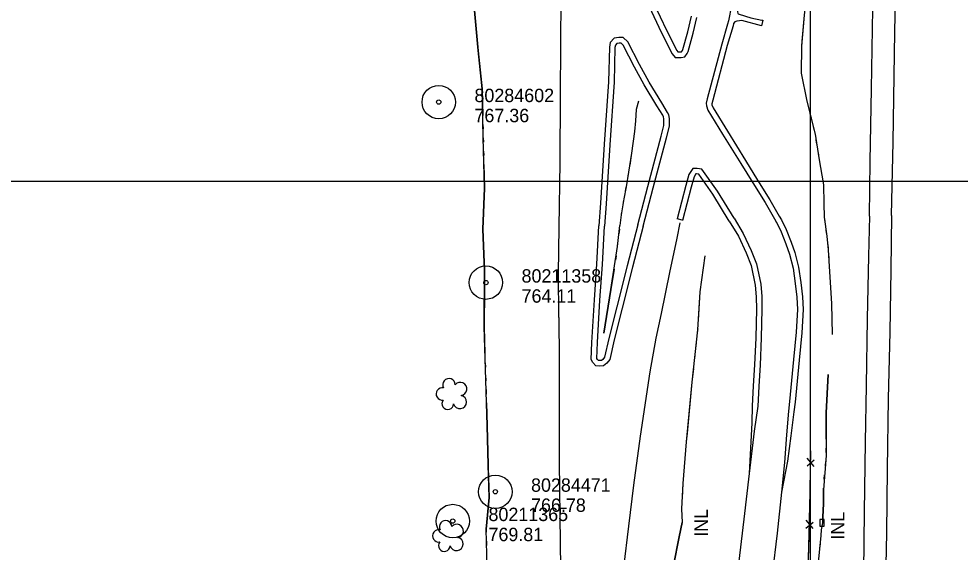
# Model space of a CAD drawing. Extents: x 591954 to 597000, y 198576 to 213500.
# Drawn here: x 593645.1 to 594067.1, y 205833.7 to 206072.7 of the extents above; entities that cross this region are included whole.
import ezdxf

# ---------------------------------------------------------------- set-up
doc = ezdxf.new("R2010")
doc.units = 0
for name, color, linetype in [('Level 10', 7, 'Continuous'), ('Level 11', 7, 'Continuous'), ('Level 15', 7, 'Continuous'), ('Level 18', 7, 'Continuous'), ('Level 19', 7, 'Continuous'), ('Level 6', 7, 'Continuous')]:
    doc.layers.add(name, color=color, linetype=linetype)

msp = doc.modelspace()

# ---------------------------------------------------------------- linework, layer by layer
at = {"layer": 'Level 10'}
for p, q in [((594000, 205500), (594000, 207000)), ((594000, 205500), (594000, 207000)), ((594000, 204500), (594000, 206500)), ((594000, 204500), (594000, 206500)), ((592000, 206000), (594000, 206000)), ((592500, 206000), (594000, 206000)), ((593000, 206000), (595500, 206000)), ((593500, 206000), (595500, 206000)), ((594000, 204500), (594000, 206000))]:
    msp.add_line(p, q, dxfattribs=at)
at = {"layer": 'Level 11'}
for points in [[(594036.36, 205984.63), (594037.09, 206017.61), (594037.84, 206066.71), (594038.65, 206112.98), (594039.48, 206154.92), (594040.21, 206199.44), (594041.34, 206246.86), (594042.45, 206288.3), (594042.69, 206328.36), (594043.65, 206372.17), (594044.47, 206414.42), (594045.26, 206451.06), (594045.9, 206490.12), (594042.53, 206442.15), (594040.23, 206416.21), (594037.67, 206395.36), (594032.38, 206363.12), (594027.04, 206332.21), (594020.01, 206298.21), (594012.21, 206264.47), (594003.31, 206227.15)], [(594026.44, 205984.26), (594026.82, 206008.76), (594027.31, 206041.38), (594027.91, 206077.18), (594028.55, 206112.9), (594029.33, 206148.91), (594029.89, 206185.65), (594030.54, 206219.18), (594031.13, 206247.37), (594031.73, 206279.29), (594032.1, 206310.06), (594029.95, 206310.68), (594024.56, 206294.57), (594019.07, 206276.15), (594014.5, 206260), (594011.42, 206248.73), (594009.55, 206240.73), (594008.71, 206234.23), (594007.98, 206226.19), (594008.2, 206220.75)], [(593911.34, 206153.74), (593911.89, 206145.39), (593912.9, 206133.22), (593913.69, 206126.34), (593914.59, 206119.55), (593916.07, 206111.56), (593917.98, 206104.55), (593920.2, 206097.24), (593923.56, 206087.73), (593927.48, 206078.49), (593933.15, 206066.49), (593938.01, 206057.04), (593939.41, 206055.46), (593941.24, 206055.39), (593941.99, 206055.42), (593943.64, 206055.67), (593944.77, 206057.25), (593945.11, 206058.12), (593947.42, 206066.22), (593949.06, 206073.3)], [(593887.38, 205979.34), (593887.77, 206008.33), (593887.92, 206038.65), (593888.27, 206083.03), (593888.85, 206120.13), (593889.03, 206137.69)], [(593929.76, 206079.52), (593935.39, 206067.59), (593940.08, 206058.46), (593940.57, 206057.92), (593941.24, 206057.89), (593941.75, 206057.91), (593942.21, 206057.98), (593942.56, 206058.46), (593942.74, 206058.93), (593945, 206066.85), (593946.62, 206073.86)], [(593964.58, 206078.75), (593963.25, 206071.77)], [(593967.08, 206078.43), (593967.1, 206076.73), (593967.24, 206075.81), (593967.42, 206075.2), (593967.63, 206075), (593968, 206074.76), (593973.21, 206073.22), (593978.2, 206072.13)], [(593963.25, 206071.77), (593962.87, 206070.27), (593960.24, 206061.42), (593953.74, 206036.82), (593953.31, 206034.9), (593953.35, 206033.76), (593954.03, 206031.72), (593960.62, 206021.08), (593968.73, 206007.91), (593974.18, 205999.17), (593979.61, 205990.36), (593983.86, 205983.03), (593984.82, 205981.41)], [(593965.54, 206070.64), (593965.28, 206069.6), (593962.65, 206060.74), (593956.17, 206036.23), (593955.82, 206034.67), (593955.84, 206034.21), (593956.31, 206032.79), (593962.75, 206022.39), (593970.85, 206009.22), (593976.3, 206000.49), (593981.75, 205991.64), (593986.02, 205984.3), (593986.97, 205982.68)], [(593977.99, 206069.6), (593969.2, 206071.92), (593968.12, 206071.88), (593967.05, 206071.68), (593966.08, 206071.33), (593965.54, 206070.64)], [(593978.2, 206072.13), (593978.58, 206072.08), (593977.99, 206069.6)], [(593924.99, 205979.79), (593929.55, 205997.02), (593935.44, 206019.44), (593936.82, 206024.59), (593936.82, 206026.22), (593936.8, 206028.05), (593936.57, 206029.64), (593935.93, 206030.79), (593933.32, 206035.06), (593927.67, 206044.35), (593923.32, 206052.29), (593918.1, 206062.44), (593916, 206064.38), (593914.03, 206064.3), (593912.03, 206064.11), (593910.26, 206062.04), (593909.88, 206060.09), (593909.52, 206044.48), (593907.56, 206016.49), (593905.84, 205990.06), (593905.18, 205979.99)], [(593922.57, 205980.43), (593927.13, 205997.65), (593933.02, 206020.08), (593934.32, 206024.92), (593934.32, 206026.21), (593934.3, 206027.86), (593934.16, 206028.83), (593933.77, 206029.53), (593931.18, 206033.76), (593925.5, 206043.1), (593921.11, 206051.11), (593916.08, 206060.9), (593915.07, 206061.84), (593914.19, 206061.8), (593913.27, 206061.71), (593912.58, 206060.91), (593912.37, 206059.82), (593912.01, 206044.36), (593910.05, 206016.32), (593908.34, 205989.89), (593907.68, 205979.82)], [(593965.76, 205983.32), (593958.38, 205995.52), (593951.34, 206005.33), (593949.15, 206005.72), (593947.22, 206005.65), (593945.47, 206002.96), (593944.16, 205997.99), (593940.18, 205983.06)], [(593963.62, 205982.03), (593956.29, 205994.14), (593949.9, 206003.05), (593948.97, 206003.21), (593948.61, 206003.2), (593947.79, 206001.93), (593946.58, 205997.35), (593942.6, 205982.41)], [(594036.36, 205984.63), (594036.07, 205960.2), (594035.59, 205932.29), (594034.81, 205902.52), (594034.32, 205870.9), (594034, 205842.33), (594033.28, 205806.43)], [(593922.57, 205980.43), (593917.82, 205962.02), (593913.14, 205943.73), (593909.57, 205929.41), (593907.67, 205921.08), (593906.97, 205920.13), (593906.3, 205919.61), (593905.49, 205919.54), (593905, 205919.59), (593904.48, 205920.12), (593904.25, 205920.57), (593904.46, 205927.64), (593905.64, 205946.58), (593906.7, 205962.61), (593907.68, 205979.82)], [(593933.22, 205940.6), (593937.02, 205959.07), (593940.19, 205974.41), (593941.6, 205981.32)], [(593942.6, 205982.41), (593942.5, 205982.44), (593940.18, 205983.06)], [(593963.62, 205982.03), (593967.68, 205975.38), (593971.14, 205967.86), (593973.39, 205962.25), (593975.2, 205953.41)], [(593965.76, 205983.33), (593969.89, 205976.55), (593973.44, 205968.85), (593975.79, 205962.97), (593977.68, 205953.77)], [(593984.73, 205981.57), (593986.87, 205977.26), (593988.95, 205971.82), (593990.6, 205967.24), (593992.23, 205960.93), (593993.2, 205954.19), (593993.91, 205947.99), (593994.16, 205942.42), (593993.6, 205932.26), (593992.41, 205920.04), (593991.47, 205910.6), (593990.58, 205901.19), (593990.1, 205896.87)], [(593986.97, 205982.68), (593989.17, 205978.27), (593991.3, 205972.69), (593992.99, 205967.97), (593994.69, 205961.42), (593995.68, 205954.51), (593996.4, 205948.19), (593996.67, 205942.41), (593996.09, 205932.07), (593994.89, 205919.79), (593993.96, 205910.36), (593993.07, 205900.93), (593992.59, 205896.59)], [(594026.44, 205984.26), (594026.07, 205966.42), (594025.43, 205938.27), (594024.9, 205908.48), (594024.53, 205883.05), (594024.07, 205851.78), (594023.71, 205825.08), (594023.22, 205804.18), (594023.02, 205787.52), (594022.46, 205770.02), (594021.35, 205749.26)], [(593887.14, 205938.88), (593887.06, 205958.58), (593887.38, 205979.34)], [(593924.99, 205979.8), (593920.24, 205961.4), (593915.56, 205943.11), (593912.01, 205928.83), (593909.99, 205920.01), (593908.78, 205918.37), (593907.24, 205917.18), (593905.48, 205917.03), (593903.83, 205917.19), (593902.43, 205918.65), (593901.73, 205920), (593901.96, 205927.75), (593903.14, 205946.74), (593904.2, 205962.76), (593905.18, 205979.96)], [(593975.2, 205953.41), (593975.67, 205948.13), (593975.76, 205942.62), (593975.46, 205929.78), (593974.93, 205917.65), (593974.36, 205908.23), (593974.08, 205902.19), (593973.92, 205899.34)], [(593977.68, 205953.77), (593978.17, 205948.26), (593978.26, 205942.61), (593977.96, 205929.7), (593977.43, 205917.52), (593976.86, 205908.1), (593976.57, 205902.06), (593976.42, 205899.21)], [(593887.14, 205938.88), (593887.35, 205919.86), (593887.34, 205874), (593887.58, 205849.78), (593887.89, 205826.52)], [(593916.28, 205826.83), (593918.5, 205845.4), (593920.85, 205863.76), (593923.73, 205885.65), (593928.11, 205914.52), (593930.82, 205929.62), (593933.22, 205940.6)], [(593976.42, 205899.21), (593974.69, 205887.93), (593972.55, 205868.98), (593970.12, 205848.46), (593967.45, 205825.91)], [(593973.92, 205899.34), (593973.69, 205891.74), (593972.55, 205868.97)], [(593990.1, 205896.87), (593989.18, 205886.33), (593988.41, 205873.93), (593986.94, 205860.59), (593985.03, 205842.18), (593982.88, 205823.75)], [(593992.59, 205896.59), (593991.25, 205885.82), (593989.62, 205874.49), (593986.94, 205860.59)]]:
    msp.add_lwpolyline(points, dxfattribs=at)
at = {"layer": 'Level 15'}
for p, q in [((593998.49, 205872.37), (594001.7, 205875.12)), ((594001.72, 205872.15), (593998.54, 205875.92)), ((593997.98, 205844.53), (594001.23, 205847.24)), ((594001.22, 205844.28), (593998.08, 205848.08))]:
    msp.add_line(p, q, dxfattribs=at)
for points in [[(593975.87, 204997.82), (593977.04, 205033.51), (593978.15, 205074.79), (593978.41, 205120.41), (593978.97, 205167.86), (593980.27, 205204.22), (593981.49, 205243.1), (593983.51, 205292.55), (593984.06, 205319.78), (593985.37, 205345.52), (593986.25, 205393.57), (593987.91, 205425.5), (593988.14, 205451.04), (593989.14, 205482.93), (593990.48, 205514.84), (593991.75, 205562.83), (593992.93, 205611.2), (593994.43, 205659.31), (593994.61, 205689.66), (593994.99, 205728.27), (593997.26, 205771.22), (593998.83, 205819.65), (593999.71, 205853.13), (594000.08, 205879.1)], [(594000.06, 205877.6), (594000.08, 205879.1)], [(593999.83, 205861.06), (593999.97, 205871.02)], [(593999.62, 205849.74), (593999.71, 205853.13), (593999.83, 205861.06)], [(594004.14, 205845.4), (594006.13, 205845.38), (594006.17, 205848.38), (594004.17, 205848.4), (594004.14, 205845.4)], [(593999.19, 205833.21), (593999.45, 205843.17)]]:
    msp.add_lwpolyline(points, dxfattribs=at)
at = {"layer": 'Level 18'}
for centre, radius, start, end in [((593837.96, 205908.71), 2.78, 1.3946, 209.1675), ((593843, 205906.85), 2.97, 278.4237, 139.6575), ((593834.96, 205904.64), 2.78, 78.0716, 279.0826), ((593837.42, 205900.24), 2.61, 140.7797, 358.7123), ((593842.89, 205901), 2.97, 196.0745, 79.0477), ((593836.41, 205845.11), 2.78, 1.3946, 209.1675), ((593841.45, 205843.25), 2.97, 278.4237, 139.6575), ((593833.41, 205841.03), 2.78, 78.0716, 279.0826), ((593835.87, 205836.64), 2.61, 140.7797, 358.7123), ((593841.34, 205837.4), 2.97, 196.0745, 79.0477)]:
    msp.add_arc(centre, radius, start, end, dxfattribs=at)
at = {"layer": 'Level 19'}
for points in [[(593853.07, 205978.46), (593853.87, 205996.89), (593853.33, 206019.68), (593852.79, 206041.38), (593850.92, 206060.09), (593849.25, 206078.09), (593849.28, 206091.01), (593849.57, 206102.56), (593849.97, 206112.88), (593851.2, 206119.82), (593851.56, 206124.49), (593851.2, 206128.39), (593850.2, 206133.72)], [(594006.34, 205983.81), (594006.2, 205990.01), (594005.92, 205998.3), (594003.88, 206010.47), (594002.2, 206021.06), (593998.47, 206035.88), (593995.92, 206048.36), (593996.05, 206060.52), (593997.32, 206074.3), (593998.68, 206086.73), (594000.41, 206098.68), (594001.74, 206107.08), (594001.44, 206120.68), (594001.17, 206127.39), (594002, 206132.17), (594001.89, 206134.66)], [(593996.26, 206062.77), (593997.32, 206074.3), (593998.68, 206086.73), (593999.39, 206091.6)], [(593849.27, 206087.26), (593849.25, 206078.09), (593850.92, 206060.09), (593851.1, 206058.34)], [(593998.92, 206034.09), (593998.47, 206035.88), (593995.92, 206048.36), (593996.05, 206060.52), (593996.26, 206062.77)], [(593851.1, 206058.34), (593852.79, 206041.38), (593853.09, 206029.43)], [(593922.96, 206035.81), (593921.89, 206032.15), (593921.53, 206026.94), (593921.12, 206022.21), (593919.8, 206012.46), (593918.45, 206003.99), (593917.31, 205997.49), (593916.26, 205992.07), (593915.11, 205984.87), (593914.54, 205980.12)], [(593922.96, 206035.81), (593921.89, 206032.15), (593921.53, 206026.94), (593921.12, 206022.21), (593919.8, 206012.46), (593918.95, 206007.15)], [(594000.38, 206028.27), (593999.9, 206030.21)], [(593853.19, 206025.43), (593853.24, 206023.43)], [(594001.84, 206022.46), (594001.36, 206024.4)], [(593853.34, 206019.43), (593853.39, 206017.43)], [(594002.91, 206016.55), (594002.6, 206018.53)], [(593853.48, 206013.43), (593853.53, 206011.44)], [(594006.34, 205983.81), (594006.2, 205990.01), (594005.92, 205998.3), (594003.88, 206010.47), (594003.54, 206012.6)], [(593853.62, 206007.44), (593853.87, 205996.89), (593853.07, 205978.46)], [(593918.32, 206003.2), (593917.97, 206001.23)], [(593917.28, 205997.29), (593916.89, 205995.33)], [(593916.15, 205991.4), (593915.84, 205989.42)], [(593915.21, 205985.47), (593915.11, 205984.87), (593914.54, 205980.12)], [(594009.89, 205931.2), (594009.57, 205945.17), (594008.7, 205959.27), (594008.13, 205969.21), (594007.46, 205975.37), (594006.34, 205983.81)], [(594006.58, 205982.06), (594006.34, 205983.81)], [(593855.29, 205821.38), (593854.62, 205844.09), (593855.98, 205858.25), (593855.53, 205872.9), (593855.07, 205890.28), (593854.43, 205910.88), (593853.71, 205934.71), (593853.92, 205959.79), (593853.07, 205978.46)], [(593853.07, 205978.46), (593853.92, 205959.79), (593853.85, 205951.56)], [(593907.44, 205931.92), (593910.52, 205951.45), (593913.52, 205970.72), (593914.54, 205980.12)], [(593914.35, 205978.4), (593914.14, 205976.41)], [(594007.36, 205976.11), (594007.1, 205978.09)], [(593913.47, 205970.45), (593913.52, 205970.72), (593913.7, 205972.43)], [(594008.03, 205970.15), (594007.81, 205972.13)], [(593912.86, 205966.49), (593912.55, 205964.52)], [(593952.58, 205966.57), (593950.35, 205950.38), (593949.42, 205933.3), (593946.82, 205909.86), (593944.33, 205883.11), (593942.73, 205864.52), (593942.21, 205853.07), (593942.48, 205846.98)], [(593952.58, 205966.57), (593950.35, 205950.38), (593949.66, 205937.74)], [(594008.42, 205964.16), (594008.3, 205966.15)], [(593911.94, 205960.57), (593910.52, 205951.45), (593907.44, 205931.92)], [(594009.89, 205931.2), (594009.57, 205945.17), (594008.7, 205959.27), (594008.64, 205960.17)], [(593853.85, 205951.56), (593853.71, 205934.71), (593854.08, 205922.57)], [(593949.45, 205933.74), (593949.42, 205933.3), (593949.25, 205931.76)], [(593948.81, 205927.78), (593948.59, 205925.79)], [(593948.15, 205921.82), (593947.93, 205919.83)], [(593854.2, 205918.57), (593854.26, 205916.57)], [(593947.49, 205915.85), (593946.82, 205909.86), (593944.69, 205886.99)], [(594007.87, 205913.36), (594006.98, 205896.12), (594006.96, 205877.09), (594005.76, 205861.65), (594005.83, 205855.85), (594005.72, 205852.12), (594005.6, 205849.83), (594005.5, 205846.8)], [(594006.97, 205884.38), (594006.98, 205896.12), (594007.87, 205913.36)], [(593854.38, 205912.57), (593854.43, 205910.88), (593854.44, 205910.57)], [(593854.56, 205906.57), (593854.63, 205904.58)], [(593854.75, 205900.58), (593855.07, 205890.28), (593855.53, 205872.9), (593855.57, 205871.59)], [(593944.69, 205886.99), (593944.33, 205883.11), (593942.73, 205864.52), (593942.44, 205858.08)], [(594006.96, 205878.38), (594006.96, 205880.38)], [(593855.57, 205871.59), (593855.98, 205858.25), (593854.62, 205844.09), (593854.67, 205842.66)], [(594006.75, 205874.39), (594006.59, 205872.4)], [(594006.13, 205866.42), (594006.28, 205868.41)], [(594005.5, 205846.8), (594005.6, 205849.83), (594005.72, 205852.12), (594005.83, 205855.85), (594005.76, 205861.65), (594005.82, 205862.43)], [(593923.92, 205503.57), (593923.52, 205534.37), (593923.26, 205565.13), (593922.74, 205590.17), (593922.47, 205618.1), (593922.69, 205648.84), (593923.31, 205674.59), (593924.33, 205703.14), (593926.79, 205732.59), (593931.08, 205771.45), (593934.09, 205796.47), (593938.6, 205827.76), (593941.2, 205840.65), (593942.48, 205846.98)], [(593942.48, 205846.98), (593941.2, 205840.65), (593938.6, 205827.76), (593937.88, 205822.74)], [(594003.46, 205827.61), (594004.79, 205841.15), (594004.94, 205843.79), (594005.5, 205846.8)], [(594004.81, 205841.46), (594004.92, 205843.45)], [(593854.78, 205838.66), (593854.84, 205836.66)], [(594004.23, 205835.49), (594004.43, 205837.48)]]:
    msp.add_lwpolyline(points, dxfattribs=at)
at = {"layer": 'Level 6'}
for centre, radius in [((593833.37, 206035.4), 7.5), ((593833.37, 206035.4), 7.5), ((593833.37, 206035.4), 7.5), ((593833.37, 206035.4), 0.96), ((593833.37, 206035.4), 0.96), ((593833.37, 206035.4), 0.96), ((593854.49, 205954.52), 7.5), ((593854.49, 205954.52), 7.5), ((593854.49, 205954.52), 7.5), ((593854.49, 205954.52), 7.5), ((593854.49, 205954.52), 0.96), ((593854.49, 205954.52), 0.96), ((593854.49, 205954.52), 0.96), ((593854.49, 205954.52), 0.96), ((593858.74, 205860.79), 7.5), ((593858.74, 205860.79), 7.5), ((593858.74, 205860.79), 7.5), ((593858.74, 205860.79), 7.5), ((593858.74, 205860.79), 0.96), ((593858.74, 205860.79), 0.96), ((593858.74, 205860.79), 0.96), ((593858.74, 205860.79), 0.96), ((593839.66, 205847.66), 7.5), ((593839.66, 205847.66), 7.5), ((593839.66, 205847.66), 7.5), ((593839.66, 205847.66), 7.5), ((593839.66, 205847.66), 0.96), ((593839.66, 205847.66), 0.96), ((593839.66, 205847.66), 0.96), ((593839.66, 205847.66), 0.96)]:
    msp.add_circle(centre, radius, dxfattribs=at)

# ---------------------------------------------------------------- texts
at = {"layer": 'Level 15'}
for p in [(593953.99, 205840.61), (594015.21, 205839.31)]:
    msp.add_text('INL', height=6, rotation=90, dxfattribs=at).set_placement(p)
at = {"layer": 'Level 6'}
for s, p in [('80284602', (593849.37, 206035.4)), ('80284602', (593849.37, 206035.4)), ('80284602', (593849.37, 206035.4)), ('767.36', (593849.37, 206026.4)), ('767.36', (593849.37, 206026.4)), ('767.36', (593849.37, 206026.4)), ('80211358', (593870.49, 205954.52)), ('80211358', (593870.49, 205954.52)), ('80211358', (593870.49, 205954.52)), ('80211358', (593870.49, 205954.52)), ('764.11', (593870.49, 205945.52)), ('764.11', (593870.49, 205945.52)), ('764.11', (593870.49, 205945.52)), ('764.11', (593870.49, 205945.52)), ('80284471', (593874.74, 205860.79)), ('80284471', (593874.74, 205860.79)), ('80284471', (593874.74, 205860.79)), ('80284471', (593874.74, 205860.79)), ('766.78', (593874.74, 205851.79)), ('766.78', (593874.74, 205851.79)), ('766.78', (593874.74, 205851.79)), ('766.78', (593874.74, 205851.79)), ('80211365', (593855.66, 205847.66)), ('80211365', (593855.66, 205847.66)), ('80211365', (593855.66, 205847.66)), ('80211365', (593855.66, 205847.66)), ('769.81', (593855.66, 205838.66)), ('769.81', (593855.66, 205838.66)), ('769.81', (593855.66, 205838.66)), ('769.81', (593855.66, 205838.66))]:
    msp.add_text(s, height=6, dxfattribs=at).set_placement(p)

doc.saveas('drawing.dxf')
